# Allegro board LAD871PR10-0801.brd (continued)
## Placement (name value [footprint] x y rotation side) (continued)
EC9717  1000P_0402_50V7K  [C_0402]  123.63 147.27 270 top
EC9719  1U_0402_10V6K  [C_0402]  95.1 114.3 0 bottom
EC9720  1U_0402_10V6K  [C_0402]  95.1 119.25 0 bottom
EC9732  1U_0402_10V6K  [C_0402]  55.04 26.61 0 bottom
EC9733  1U_0402_10V6K  [C_0402]  158.18 52.01 180 top
EC9735  1U_0402_10V6K  [C_0402]  83.95 152.53 180 bottom
EC9736  1U_0402_10V6K  [C_0402]  83.95 149.73 180 bottom
EC9755  0.1U_0402_25V6  [C_0402]  167.88 120.47 315 bottom
EC9756  0.1U_0402_25V6  [C_0402]  168.9 121.35 315 bottom
EC9758  10P_0402_50V8J  [C_0402]  30.17 18.48 180 top
EC9759  0.1U_0402_25V6  [C_0402]  71.15 158.41 180 top
EC9760  0.1U_0402_25V6  [C_0402]  50.54 63.26 180 bottom
ED6101  -  [AZ5725-01F_DFN2]  192 175.07 180 top
EU3101  -  [TVWDF1004AD0_DFN9]  36.92 173.15 90 bottom
EU3102  -  [TVWDF1004AD0_DFN9]  37.28 173.15 90 top
EU3403  -  [AZC199-02SPR7G_SOT23-3]  22.07 38.07 90 top
EU5602  -  [L05ESDL5V0NA-4_SLP2510P8-10-9]  185.7 32.62 270 bottom
F5201  SMD1812P150TF/24 1.5A UL/CSA/TUV  [F_SMD1812P110TF-24]  73.07 162.18 0 bottom
F5203  1.1A_24V_SMD1812P110TF-24  [F_SMD1812P110TF-24]  92.25 153.35 0 bottom
F5501  1.1A_6V_SPR-P110  [F_SPR-P110]  19.02 70.23 0 top
F6201  0.5A_13.2V_NANOSMDC050F-13.2-2  [F_NANOSMDC050F-13P2-2]  183.8 119.89 180 bottom
FAN1  E-T_3703K-Q03N-11L  [E-T_3703K-Q03N-11L_3P]  92.47 136.72 24.9 bottom
FAN261  -  [APL5606AKI-TRG_SO8]  97.95 143.73 90 bottom
FD1  FIDUCAL  [FIDUCIAL_C40M80]  30.46 5.36 180 bottom
FD2  FIDUCIAL  [FIDUCIAL_C40M80]  38.79 10.62 0 top
FD3  FIDUCAL  [FIDUCIAL_C40M80]  201.54 177.23 180 bottom
FD4  FIDUCIAL  [FIDUCIAL_C40M80]  201.54 177.23 0 top
FD5  FIDUCAL  [FIDUCIAL_C40M80]  66.33 170 0 top
FD6  FIDUCIAL  [FIDUCIAL_C40M80]  200.34 3.17 180 bottom
G6101  GAP-OPEN  [SHORTPADS]  193.6 173.35 180 top
G6102  GAP-OPEN  [SHORTPADS]  191.4 176.05 270 bottom
H1  H_3P2  [H_3P2-G]  142.05 165.77 0 top
H2  H_3P0  [H_3P0-G]  169.65 12.77 0 top
H3  H_3P0  [H_3P0-G]  20.65 50.77 0 top
H4  H_3P0  [H_3P0-G]  96.65 128.47 0 top
H5  H_3P0  [H_3P0-G]  37.75 164.77 0 top
H6  H_3P2  [H_3P2-G]  199.85 56.27 0 top
H7  H_3P0  [H_3P0-G]  154.25 60.97 0 top
H8  -  [H_4P0N]  148.45 163.97 0 top
H9  -  [H_3P0X3P8N]  6.15 79.07 90 top
HCPU1  -  [H_3P7]  145.35 70.77 0 top
HCPU2  -  [H_3P7]  90.95 70.77 0 top
HCPU3  -  [H_3P4]  118.15 105.07 0 top
HDA27  ALC3246-CG_MQFN_48P  [ALC3234-CG_MQFN48_6X6-S]  180.52 14.09 90 bottom
HDD1  ACES_51625-01201-001  [ACES_51625-01201-001_12P]  191.37 33.63 270 bottom
HGPU1  -  [H_3P3]  143.25 148.69 0 top
HGPU2  -  [H_3P3]  201.25 114.27 0 bottom
HGPU3  -  [H_3P3]  200.85 158.69 180 bottom
J10  PAD-OPEN1X2M  [JUMP_43X39]  139.38 153.24 270 top
J11  -  [JUMP_43X118]  147.72 154.37 0 top
J12  -  [JUMP_43X118]  187.8 120.27 180 bottom
JCRT  C-K_80461-5K1-152  [C-K_80461-5K1-152_15P-T]  13.8 60.89 90 bottom
JDEG1  ACES_51522-01001-001  [ACES_51522-01001-001_10P]  191.95 90.11 270 bottom
JDIMM1  DEREN_40-42271-26001RHF  [DEREN_40-42271-26001RHF_260P-T]  78.12 38.99 0 bottom
JDIMM2  DEREN_40-42261-26001RHF  [DEREN_40-42261-26001RHF_260P-T]  86.72 24.66 180 bottom
JHDMI  ACON_HMRBK-AK120C~D  [C-K_96067-3K28-192-124_19P]  9.9 60.72 90 bottom
JWDB1  CVILU_CI1804M1VRA-NH  [CVILU_CI1804M1VRA-NH_4P]  155.85 51.8 180 bottom
KB1  CVILU_CF32301D0R0-NH  [CVILU_CF32301D0R0-NH_30P-T]  192.05 116.15 270 top
KB_BL1  E-T_6913K-Y04N-00L  [E-T_6913K-Y04N-00L_4P]  192.05 121.57 90 top
L3001  4.7UH_ZADH-252012MES-4R7M  [ZEN_ZADH-252012MES-4R7M_2P]  52.7 174.12 90 top
L5501  CHILISIN NBQ160808T-800Y-N 0603  [MURAT_BLM18BB221SN1D_2P]  22.14 61.88 180 top
L5502  CHILISIN NBQ160808T-800Y-N 0603  [MURAT_BLM18BB221SN1D_2P]  22.14 64.04 180 top
L5503  CHILISIN NBQ160808T-800Y-N 0603  [MURAT_BLM18BB221SN1D_2P]  22.14 59.15 180 top
LCD1  ACES_51540-04001-P01  [ACES_51540-04001-P01_40P]  80.8 165.93 0 bottom
LED1  12-22A/Y2T7D-C30/2C YELLOW/WHITE  [LED_12-22A-S2ST3D-C30-2C_3P]  16.54 1.78 180 top
LOM30  RTL8106E-CG_QFN32_4X4  [RTL8106E-CG_QFN32_4X4-S]  47.23 170.4 270 top
LV2  BLM15BD121SN1D_0402  [R_0402]  151.82 125.6 315 top
LV3  BLM15BD121SN1D_0402  [R_0402]  149.41 128.27 315 top
LV4  BLM15BD121SN1D_0402  [R_0402]  151.06 124.46 135 bottom
LV6  BLM15BD221SN1D_2P  [MURAT_BLM15BB221SN1D_2P]  171 129.54 135 top
LV7  BLM15BD121SN1D_0402  [R_0402]  178.11 128.91 45 top
LV8  BLM15BD121SN1D_0402  [R_0402]  178.86 128.13 45 top
NOREF  -  []  93.9 -40.25 0 top
NOREF#2  -  []  84.55 55.6 0 top
NOREF#3  -  []  200.85 158.69 0 top
NOREF#4  -  []  201.25 114.27 270 top
NOREF#5  -  []  54.41 5.27 0 top
NOREF#6  -  []  96.65 128.47 90 top
NOREF#7  -  []  143.25 148.69 0 top
NOREF#8  -  []  90.95 70.77 270 top
NOREF#9  -  []  107.75 60.79 0 top
NOREF#10  -  []  142.05 165.77 0 top
NOREF#11  -  []  8.96 446.38 0 top
NOREF#12  -  []  20.65 50.77 90 top
NOREF#13  -  []  146.42 8.76 0 top
NOREF#14  -  []  196.65 5.01 0 top
NOREF#15  -  []  169.65 12.77 270 top
NOREF#16  -  []  145.35 70.77 90 top
NOREF#17  -  []  118.15 105.07 270 top
NOREF#18  -  []  169.65 12.77 0 top
NOREF#19  -  []  154.25 60.97 0 top
NOREF#20  -  []  37.75 164.77 180 top
NOREF#21  -  []  4.72 257.97 0 top
NOREF#22  -  []  99.31 13.27 0 top
NOREF#23  -  []  201.25 114.27 0 top
NOREF#24  -  []  200.85 158.67 270 top
NOREF#25  -  []  96.65 128.47 90 top
NOREF#26  -  []  199.85 56.27 0 top
NOREF#27  -  []  90.35 76.83 180 bottom
NOREF#28  -  []  197.07 177.44 180 bottom
NOREF#29  -  []  143.25 148.67 90 bottom
NOREF#30  -  []  82.83 48.61 180 bottom
NOREF#31  -  []  213.55 158.67 90 bottom
NOREF#32  -  []  131.95 53.86 180 bottom
ODD1  ACES_51519-02001-P01  [ACES_51519-02001-P01_20P]  155.4 76.58 90 top
PBATT1  SUYIN_200277GR008M270ZR  [SUYIN_200277GR008M270ZR_8P-T]  152.4 179.77 0 bottom
PC1  1000P_0402_50V7K  [C_0402]  83.33 158.08 270 top
PC2  2200P_0402_25V7K  [C_0402]  82.44 158.08 270 top
PC3  1000P_0402_50V7K  [C_0402]  76.63 158.94 270 top
PC4  2200P_0402_25V7K  [C_0402]  77.51 158.94 270 top
PC7  0.01U_0402_25V7K  [C_0402]  150.48 172.59 0 top
PC8  1000P_0402_50V7K  [C_0402]  153.17 172.59 180 top
PC14  .1U_0402_16V7K  [C_0402]  146.49 171.15 270 top
PC16  .1U_0402_16V7K  [C_0402]  118.29 168.83 90 top
PC100  0.1U_0402_25V6  [C_0402]  31.92 43.24 0 bottom
PC102  0.1U_0402_10V7K  [C_0402]  28.79 36.46 0 bottom
PC103  2200P_0402_50V7K  [C_0402]  31.92 44.2 0 bottom
PC104  10U_0805_25V6K~D  [C_0805]  31.11 41.87 0 bottom
PC105  10U_0805_25V6K~D  [C_0805]  31.11 41.87 0 top
PC106  22U_0805_6.3V6M  [C_0805]  36.61 26.77 0 bottom
PC107  22U_0805_6.3V6M  [C_0805]  36.33 30 90 bottom
PC108  22U_0805_6.3V6M  [C_0805]  36.63 28.47 0 bottom
PC109  22U_0805_6.3V6M  [C_0805]  34.54 26.52 0 top
PC110  22U_0805_6.3V6M  [C_0805]  34.61 29.98 90 bottom
PC111  4.7U_0603_6.3V6M  [C_0603]  37.88 36.68 270 bottom
PC112  680P_0603_50V7K  [C_0603]  36.71 35.13 180 bottom
PC113  1000P_0402_25V8J  [C_0402]  37.05 40.68 0 bottom
PC114  0.1U_0402_10V7K  [C_0402]  40.39 36.45 0 bottom
PC115  0.1U_0402_25V6  [C_0402]  43.47 43.08 0 bottom
PC116  2200P_0402_50V7K  [C_0402]  43.47 43.97 0 bottom
PC117  10U_0805_25V6K~D  [C_0805]  42.58 41.76 0 bottom
PC118  10U_0805_25V6K~D  [C_0805]  42.59 41.75 0 top
PC119  4.7U_0603_6.3V6M  [C_0603]  48.65 35.86 0 bottom
PC120  22U_0805_6.3V6M  [C_0805]  47.86 27.81 270 bottom
PC121  22U_0805_6.3V6M  [C_0805]  49.59 27.81 270 bottom
PC122  22U_0805_6.3V6M  [C_0805]  51.72 31.95 0 bottom
PC123  22U_0805_6.3V6M  [C_0805]  47.78 29.24 90 bottom
PC124  22U_0805_6.3V6M  [C_0805]  49.64 29.24 90 bottom
PC125  680P_0603_50V7K  [C_0603]  48.57 34.67 180 bottom
PC126  4.7U_0603_6.3V6M  [C_0603]  48.65 37.08 0 bottom
PC127  1000P_0402_25V8J  [C_0402]  48.77 40.72 0 bottom
PC128  4.7U_0402_6.3V6M  [C_0402]  48.7 41.02 0 top
PC130  0.1U_0402_25V6  [C_0402]  31.87 44.14 0 top
PC131  2200P_0402_50V7K  [C_0402]  31.86 43.18 0 top
PC132  0.1U_0402_25V6  [C_0402]  43.43 43.95 0 top
PC133  2200P_0402_50V7K  [C_0402]  43.41 43.05 0 top
PC200  0.1U_0402_10V7K  [C_0402]  63.05 17.84 180 top
PC201  2200P_0402_50V7K  [C_0402]  69.64 19.43 0 bottom
PC202  0.1U_0402_10V7K  [C_0402]  55.31 22.19 180 top
PC203  0.1U_0402_10V7K  [C_0402]  55.31 23.08 180 top
PC204  1U_0603_10V6K  [C_0603]  57.78 15.88 90 top
PC205  10U_0805_6.3V6K  [C_0805]  62.48 21.65 0 top
PC206  10U_0805_25V6K~D  [C_0805]  69.44 16.19 0 top
PC207  680P_0402_50V7K  [C_0402]  71.68 21.97 270 bottom
PC208  0.1U_0402_25V6  [C_0402]  69.64 20.32 0 bottom
PC209  1U_0603_10V6K  [C_0603]  55.3 18.48 180 top
PC210  0.033U_0402_16V7K  [C_0402]  58.1 24.19 90 top
PC211  10U_0805_6.3V6K  [C_0805]  62.48 23.43 0 top
PC212  10U_0805_25V6K~D  [C_0805]  69.44 17.97 0 top
PC213  .1U_0402_16V7K  [C_0402]  57.22 25.97 180 top
PC214  220P_0402_25V8J  [C_0402]  56.31 24.19 0 top
PC215  22U_0603_6.3V6M  [C_0603]  77.21 22.99 180 top
PC216  22U_0603_6.3V6M  [C_0603]  80.19 22.99 0 top
PC217  22U_0603_6.3V6M  [C_0603]  80.19 21.72 0 top
PC218  22U_0603_6.3V6M  [C_0603]  80.19 20.45 0 top
PC219  22U_0603_6.3V6M  [C_0603]  77.21 20.32 180 top
PC220  22U_0603_6.3V6M  [C_0603]  77.21 21.65 180 top
PC230  0.1U_0402_25V6  [C_0402]  69.65 20.33 0 top
PC231  2200P_0402_50V7K  [C_0402]  69.65 19.4 0 top
PC301  2200P_0402_50V7K  [C_0402]  129.27 130.49 0 top
PC302  0.1U_0402_25V6  [C_0402]  129.28 129.55 0 top
PC303  10U_0805_25V6K~D  [C_0805]  129.15 128.04 0 bottom
PC304  0.1U_0402_25V6  [C_0402]  131.95 127.51 90 top
PC305  1U_0402_6.3V6K  [C_0402]  134.3 123.44 0 bottom
PC306  2.2U_0402_6.3V6M  [C_0402]  134.3 122.49 0 bottom
PC307  0.1U_0402_10V7K  [C_0402]  126.65 122.83 0 bottom
PC308  680P_0603_50V7K  [C_0603]  126.88 117.64 270 bottom
PC309  330P_0402_50V7K  [C_0402]  134.35 125.31 90 bottom
PC310  22U_0603_6.3V6M  [C_0603]  134.47 114.16 180 bottom
PC311  22U_0603_6.3V6M  [C_0603]  134.47 115.37 180 bottom
PC312  22U_0603_6.3V6M  [C_0603]  136.49 118.64 90 top
PC313  22U_0603_6.3V6M  [C_0603]  136.51 118.66 90 bottom
PC320  2200P_0402_50V7K  [C_0402]  129.28 130.49 0 bottom
PC321  0.1U_0402_25V6  [C_0402]  129.28 129.54 0 bottom
PC501  22U_0603_6.3V6M  [C_0603]  169.73 23.62 90 bottom
PC502  0.1U_0402_10V7K  [C_0402]  175.44 25.67 270 bottom
PC503  22P_0402_50V8J  [C_0402]  174.53 23.7 270 bottom
PC504  680P_0402_50V7K  [C_0402]  168.85 31.69 180 bottom
PC505  22U_0603_6.3V6M  [C_0603]  175.76 33.85 0 bottom
PC506  22U_0603_6.3V6M  [C_0603]  175.75 32.58 0 bottom
PC507  22U_0603_6.3V6M  [C_0603]  175.76 31.3 0 bottom
PC601  680P_0402_50V7K  [C_0402]  122.99 137.55 90 top
PC602  0.1U_0402_25V6  [C_0402]  114.75 144.48 180 bottom
PC603  1U_0603_10V6K  [C_0603]  115.97 143.7 270 bottom
PC604  0.22U_0603_25V7K  [C_0603]  123.63 145.67 270 bottom
PC605  47P_0402_50V8J~D  [C_0402]  110.41 145.8 0 bottom
PC606  33U_25V_M  [C_25CL33LD]  106.48 127.8 270 bottom
PC608  10U_0805_25V6K~D  [C_0805]  120.07 127.89 0 top
PC611  0.22U_0402_16V7K  [C_0402]  120.01 131.76 90 bottom
PC612  10U_0805_25V6K~D  [C_0805]  119.98 127.89 0 bottom
PC613  330P_0402_50V8J  [C_0402]  114.3 141.83 180 bottom
PC614  2200P_0402_50V7K  [C_0402]  114.28 140.08 270 bottom
PC616  33P_0402_50V8J  [C_0402]  114.31 140.93 180 bottom
PC617  220P_0402_50V7K  [C_0402]  110.04 139.7 180 top
PC618  330P_0402_50V7K  [C_0402]  110.93 144.37 270 bottom
PC619  0.01U_0402_50V7K  [C_0402]  111.82 144.37 270 bottom
PC620  0.082U_0402_16V7K  [C_0402]  110.92 142.58 0 bottom
PC621  1000P_0402_50V7K  [C_0402]  111.01 142.52 180 top
PC622  680P_0603_50V7K  [C_0603]  124.33 122.3 90 bottom
PC624  0.01U_0402_16V7K  [C_0402]  111.94 139.2 270 bottom
PC625  330P_0402_50V7K  [C_0402]  115.69 138.02 270 bottom
PC626  0.1U_0402_25V7K  [C_0402]  111.05 139.2 270 bottom
PC627  2200P_0402_50V7K  [C_0402]  110.98 138.71 0 top
PC628  10P_0402_50V8J  [C_0402]  119.5 140.2 180 bottom
PC629  2200P_0402_50V7K  [C_0402]  119.26 137.35 180 bottom
PC630  2200P_0402_50V7K  [C_0402]  119.87 135.47 0 top
PC631  1200P_0402_50V7K  [C_0402]  118.56 142.08 270 bottom
PC632  2200P_0402_25V7K  [C_0402]  121.14 141.44 0 top
PC633  6800P_0402_25V7K  [C_0402]  121.2 141.5 0 bottom
PC635  0.022U_0402_16V7K  [C_0402]  110.99 136.93 0 top
PC636  33P_0402_50V8J  [C_0402]  116.58 137.92 270 bottom
PC637  0.033U_0402_16V7K  [C_0402]  121.2 143.28 0 bottom
PC638  0.022U_0402_16V7K  [C_0402]  110.99 135.79 0 top
PC639  2200P_0402_25V7K  [C_0402]  116.82 134.57 270 top
PC640  2200P_0402_25V7K  [C_0402]  122.11 139.39 90 top
PC641  .1U_0402_16V7K  [C_0402]  109.28 138.29 90 bottom
PC642  0.068U_0402_16V7K  [C_0402]  119.97 135.46 270 bottom
PC643  330P_0402_50V7K  [C_0402]  119.5 139.31 180 bottom
PC644  .1U_0402_16V7K  [C_0402]  122.1 144.2 90 bottom
PC645  .1U_0402_16V7K  [C_0402]  120.85 134.72 0 bottom
PC646  0.033U_0402_16V7K  [C_0402]  119.08 135.46 270 bottom
PC647  680P_0402_50V7K  [C_0402]  118.12 132.77 180 top
PC649  0.01U_0402_50V7K  [C_0402]  122.05 137.54 180 bottom
PC650  0.082U_0402_16V7K  [C_0402]  121.22 139.42 270 bottom
PC651  330P_0402_50V7K  [C_0402]  118.1 133.68 90 top
PC652  330P_0402_50V7K  [C_0402]  122.11 139.42 270 bottom
PC653  0.082U_0402_16V7K  [C_0402]  118.09 135.47 0 top
PC654  0.01U_0402_50V7K  [C_0402]  118.99 133.68 90 top
PC655  0.22U_0402_16V7K  [C_0402]  115.5 130.75 270 bottom
PC656  10U_0805_25V6K~D  [C_0805]  115.88 127.2 270 bottom
PC657  10U_0805_25V6K~D  [C_0805]  117.63 127.2 270 bottom
PC658  10U_0805_25V6K~D  [C_0805]  115.82 127.22 270 top
PC659  0.1U_0402_25V6K~D  [C_0402]  119.06 126.62 270 top
PC660  2200P_0402_50V7K  [C_0402]  117.21 126.63 270 top
PC661  1U_0402_10V6K  [C_0402]  113.09 129.54 90 bottom
PC662  680P_0603_50V7K  [C_0603]  110.99 122.68 90 top
PC663  0.22U_0402_16V7K  [C_0402]  58.32 43.89 90 bottom
PC664  10U_0805_25V6K~D  [C_0805]  58.1 46.86 90 top
PC665  10U_0805_25V6K~D  [C_0805]  57.92 46.86 90 bottom
PC666  0.1U_0402_25V6K~D  [C_0402]  63.23 40.88 90 bottom
PC667  2200P_0402_50V7K  [C_0402]  64.12 40.88 90 bottom
PC668  0.1U_0402_25V6K~D  [C_0402]  56.6 46.99 90 bottom
PC669  1U_0402_10V6K  [C_0402]  62.03 44.15 0 bottom
PC670  680P_0603_50V7K  [C_0603]  59.04 51.46 270 top
PC671  0.22U_0402_16V7K  [C_0402]  67.11 36.45 90 bottom
PC672  10U_0805_25V6K~D  [C_0805]  65.59 39.98 90 top
PC673  10U_0805_25V6K~D  [C_0805]  65.46 39.98 90 bottom
PC674  2200P_0402_50V7K  [C_0402]  55.71 46.99 90 bottom
PC677  1U_0402_10V6K  [C_0402]  69.78 37.35 270 bottom
PC678  680P_0603_50V7K  [C_0603]  70.8 45.34 270 top
PC679  1000P_0402_50V7K  [C_0402]  63.24 40.88 90 top
PC680  1000P_0402_50V7K  [C_0402]  118.1 126.63 270 top
PC681  1000P_0402_50V7K  [C_0402]  54.82 46.99 90 bottom
PC682  2200P_0402_50V7K  [C_0402]  55.89 46.99 90 top
PC683  0.1U_0402_25V6K~D  [C_0402]  56.78 46.99 90 top
PC684  0.1U_0402_25V6  [C_0402]  71.82 39.71 270 bottom
PC685  1U_0402_10V6K  [C_0402]  124.2 129.34 90 bottom
PC686  10P_0402_25V8J  [C_0402]  108.39 126.24 270 top
PC687  10P_0402_25V8J  [C_0402]  55 46.99 90 top
PC688  10P_0402_25V8J  [C_0402]  64.19 40.88 90 top
PC690  33U_25V_M  [C_25CL33LD]  61.96 38.02 180 bottom
PC691  2200P_0402_50V7K  [C_0402]  109.28 126.24 270 top
PC692  0.1U_0402_25V6K~D  [C_0402]  59.58 41.96 0 bottom
PC693  2200P_0402_50V7K  [C_0402]  59.58 42.84 0 bottom
PC694  0.1U_0402_25V6K~D  [C_0402]  118.93 126.62 270 bottom
PC695  10P_0402_25V8J  [C_0402]  114.85 146.49 0 top
PC705  2200P_0402_25V7K  [C_0402]  120.97 152.84 180 top
PC708  0.1U_0402_25V6  [C_0402]  109.82 162.77 0 bottom
PC711  0.01UF_0402_25V7K  [C_0402]  80.07 169.21 90 top
PC721  0.22U_0402_16V7K  [C_0402]  116.02 157.35 180 bottom
PC742  5600P_0402_25V7K  [C_0402]  78.52 164.47 180 top
PC744  0.1U_0402_25V6  [C_0402]  78.52 166.5 180 top
PC747  0.1U_0402_25V6  [C_0402]  108.46 154.81 180 bottom
PC748  0.1U_0402_25V7K  [C_0402]  104.07 158.83 270 bottom
PC749  0.1U_0402_25V7K  [C_0402]  104.07 160.6 270 bottom
PC750  0.22U_0603_25V7K  [C_0603]  110.74 154.69 180 bottom
PC751  560P_0402_50V7K  [C_0402]  103.68 162.75 0 bottom
PC752  0.015U_0402_25V7K  [C_0402]  103.68 163.64 0 bottom
PC753  10P_0402_50V8J  [C_0402]  109.91 160.32 90 top
PC757  1U_0603_25V6  [C_0603]  114.36 159.32 90 bottom
PC760  10U_0805_25V6K~D  [C_0805]  124.63 157.4 0 top
PC761  10U_0805_25V6K~D  [C_0805]  135.67 162.28 90 bottom
PC762  10U_0805_25V6K~D  [C_0805]  124.55 153.87 0 top
PC763  10U_0805_25V6K~D  [C_0805]  124.63 155.63 0 top
PC764  10U_0805_25V6K~D  [C_0805]  124.55 152.15 0 top
PC765  0.1U_0402_25V7K  [C_0402]  120.97 153.73 180 top
PC766  10U_0805_25V6K~D  [C_0805]  132.11 162.28 90 bottom
PC767  680P_0603_50V7K  [C_0603]  126.23 162.75 270 top
PC768  1U_0402_16V6K  [C_0402]  111.82 159.44 90 top
PC769  1U_0402_16V6K  [C_0402]  111.68 158.56 0 top
PC775  10U_0805_25V6K~D  [C_0805]  133.91 162.28 90 bottom
PC776  10U_0805_25V6K~D  [C_0805]  135.79 160.78 0 bottom
PC777  0.1U_0402_25V7K  [C_0402]  134.75 158.83 270 bottom
PC778  10U_0805_25V6K~D  [C_0805]  135.82 159.03 0 bottom
PC779  0.1U_0402_25V7K  [C_0402]  130.97 155.87 270 top
PC780  0.1U_0402_25V7K  [C_0402]  121.03 150.93 180 top
PC781  2200P_0402_25V7K  [C_0402]  121.03 151.89 180 top
PC790  0.047U_0402_16V7K  [C_0402]  68.13 160.91 270 top
PC801  1U_0402_6.3V6K  [C_0402]  59.23 33.05 0 bottom
PC802  10U_0805_10V6K  [C_0805]  57.7 30.5 90 bottom
PC803  0.01U_0402_25V7K  [C_0402]  66.51 30.49 270 bottom
PC804  10U_0805_10V6K  [C_0805]  67.03 31.71 90 bottom
PC805  0.1U_0402_10V6K  [C_0402]  57.21 29.22 270 bottom
PC836  330U_2V_M  [C_5X4P5]  188.74 95.97 90 bottom
PC837  330U_2V_M  [C_5X4P5]  188.06 100.96 180 bottom
PC838  330U_2V_M  [C_5X4P5]  188.06 107.06 180 bottom
PC839  330U_2V_M  [C_5X4P5]  186.28 113.16 180 bottom
PC1001  22U_0603_6.3V6M  [C_0603]  115.99 88.71 0 top
PC1002  22U_0603_6.3V6M  [C_0603]  115.99 89.92 0 top
PC1003  22U_0603_6.3V6M  [C_0603]  106.94 112.26 0 top
PC1004  22U_0603_6.3V6M  [C_0603]  118.4 86.3 0 top
PC1005  22U_0603_6.3V6M  [C_0603]  101.13 111.38 0 top
PC1006  22U_0603_6.3V6M  [C_0603]  110.18 112.33 0 top
PC1007  22U_0603_6.3V6M  [C_0603]  101.15 110.05 0 top
PC1008  22U_0603_6.3V6M  [C_0603]  113.23 112.07 0 top
PC1009  22U_0603_6.3V6M  [C_0603]  105.04 109.66 180 top
PC1010  22U_0603_6.3V6M  [C_0603]  115.99 85.03 0 top
PC1011  22U_0603_6.3V6M  [C_0603]  114.85 87.5 180 top
PC1012  22U_0603_6.3V6M  [C_0603]  118.4 85.03 0 top
PC1013  22U_0603_6.3V6M  [C_0603]  110.18 107.25 0 top
PC1014  22U_0603_6.3V6M  [C_0603]  95.26 86.32 90 top
PC1015  22U_0603_6.3V6M  [C_0603]  61.72 68.64 180 top
PC1016  22U_0603_6.3V6M  [C_0603]  83.36 83.22 135 bottom
PC1017  22U_0603_6.3V6M  [C_0603]  61.68 69.89 180 bottom
PC1018  22U_0603_6.3V6M  [C_0603]  80.38 78.61 315 bottom
PC1019  22U_0603_6.3V6M  [C_0603]  61.69 68.64 180 bottom
PC1020  22U_0603_6.3V6M  [C_0603]  87.78 86.3 90 top
PC1021  22U_0603_6.3V6M  [C_0603]  90.25 86.3 90 top
PC1022  22U_0603_6.3V6M  [C_0603]  110.97 90.58 270 top
PC1023  22U_0603_6.3V6M  [C_0603]  81.27 79.44 315 top
PC1024  22U_0603_6.3V6M  [C_0603]  92.72 86.32 90 top
PC1025  22U_0603_6.3V6M  [C_0603]  91.56 89.38 90 top
PC1026  22U_0603_6.3V6M  [C_0603]  108.19 82.47 90 top
PC1027  22U_0603_6.3V6M  [C_0603]  108.56 80.8 0 top
PC1028  22U_0603_6.3V6M  [C_0603]  96.41 89.37 90 top
PC1029  22U_0603_6.3V6M  [C_0603]  93.99 89.37 90 top
PC1030  1U_0201_6.3V6M  [C_0201]  115.89 82.75 180 top
PC1031  1U_0201_6.3V6M  [C_0201]  120.86 87.59 0 top
PC1032  1U_0201_6.3V6M  [C_0201]  114.64 82.78 180 top
PC1033  1U_0201_6.3V6M  [C_0201]  117.58 82.8 0 top
PC1034  1U_0201_6.3V6M  [C_0201]  101.11 107.38 0 top
PC1035  1U_0201_6.3V6M  [C_0201]  120.21 93.52 180 top
PC1036  1U_0201_6.3V6M  [C_0201]  101.11 105.47 0 top
PC1037  1U_0201_6.3V6M  [C_0201]  120.86 88.23 0 top
PC1038  1U_0201_6.3V6M  [C_0201]  119.14 81.1 180 top
PC1039  1U_0201_6.3V6M  [C_0201]  101.11 106.74 0 top
PC1040  1U_0201_6.3V6M  [C_0201]  105.24 76.83 0 top
PC1041  1U_0201_6.3V6M  [C_0201]  107.29 81.15 270 top
PC1042  1U_0201_6.3V6M  [C_0201]  105.94 73.34 0 top
PC1043  1U_0201_6.3V6M  [C_0201]  102.08 95.19 180 top
PC1044  1U_0201_6.3V6M  [C_0201]  101.82 76.33 180 top
PC1045  1U_0201_6.3V6M  [C_0201]  111.61 81.17 270 top
PC1046  1U_0201_6.3V6M  [C_0201]  98.82 91 0 top
PC1047  1U_0201_6.3V6M  [C_0201]  112.79 82.33 0 top
PC1048  1U_0201_6.3V6M  [C_0201]  112.79 82.91 0 top
PC1049  1U_0201_6.3V6M  [C_0201]  100.3 97.98 180 top
PC1050  1U_0201_6.3V6M  [C_0201]  120.26 92.46 180 top
PC1051  1U_0201_6.3V6M  [C_0201]  117.72 81.1 180 top
PC1052  1U_0201_6.3V6M  [C_0201]  120.44 81 0 top
PC1053  1U_0201_6.3V6M  [C_0201]  119.14 80.54 180 top
PC1054  1U_0201_6.3V6M  [C_0201]  117.72 80.54 180 top
PC1055  1U_0201_6.3V6M  [C_0201]  112.47 81.17 270 top
PC1056  1U_0201_6.3V6M  [C_0201]  105.94 75.18 0 top
PC1057  22U_0603_6.3V6M  [C_0603]  123.61 89.81 180 top
PC1058  22U_0603_6.3V6M  [C_0603]  124.56 87.97 0 top
PC1059  22U_0603_6.3V6M  [C_0603]  119.29 111.51 180 top
PC1060  22U_0603_6.3V6M  [C_0603]  123.63 111.4 180 top
PC1061  22U_0603_6.3V6M  [C_0603]  105.04 110.93 180 top
PC1062  330U_2V_M  [C_5X4P5]  108.04 106.41 0 bottom
PC1063  330U_2V_M  [C_5X4P5]  66.05 57.26 180 bottom
PC1064  22U_0603_6.3V6M  [C_0603]  101.15 108.71 0 top
PC1065  22U_0603_6.3V6M  [C_0603]  105.04 112.2 180 top
PC1066  22U_0603_6.3V6M  [C_0603]  114.85 83.82 180 top
PC1067  22U_0603_6.3V6M  [C_0603]  118.4 83.82 0 top
PC1068  22U_0603_6.3V6M  [C_0603]  106.94 110.99 0 top
PC1069  22U_0603_6.3V6M  [C_0603]  114.85 86.3 180 top
PC1070  22U_0603_6.3V6M  [C_0603]  106.94 107.18 0 top
PC1071  22U_0603_6.3V6M  [C_0603]  105.08 107.11 180 top
PC1072  22U_0603_6.3V6M  [C_0603]  106.94 108.45 0 top
PC1073  22U_0603_6.3V6M  [C_0603]  113.23 110.8 0 top
PC1074  22U_0603_6.3V6M  [C_0603]  118.4 89.92 0 top
PC1075  22U_0603_6.3V6M  [C_0603]  110.18 111.06 0 top
PC1076  22U_0603_6.3V6M  [C_0603]  110.18 109.79 0 top
PC1077  22U_0603_6.3V6M  [C_0603]  105.04 108.39 180 top
PC1078  22U_0603_6.3V6M  [C_0603]  118.4 88.71 0 top
PC1079  22U_0603_6.3V6M  [C_0603]  114.85 88.71 180 top
PC1080  22U_0603_6.3V6M  [C_0603]  106.94 109.72 0 top
PC1081  22U_0603_6.3V6M  [C_0603]  114.85 85.03 180 top
PC1082  22U_0603_6.3V6M  [C_0603]  115.99 86.3 0 top
PC1083  1U_0201_6.3V6M  [C_0201]  106.17 104.53 0 top
PC1084  1U_0201_6.3V6M  [C_0201]  118.99 93.62 180 top
PC1085  1U_0201_6.3V6M  [C_0201]  101.11 106.11 0 top
PC1086  1U_0201_6.3V6M  [C_0201]  114.95 92.43 180 top
PC1087  1U_0201_6.3V6M  [C_0201]  115.79 93.52 0 top
PC1088  1U_0201_6.3V6M  [C_0201]  120.86 88.86 0 top
PC1089  1U_0201_6.3V6M  [C_0201]  106.14 105.79 0 top
PC1090  1U_0201_6.3V6M  [C_0201]  120.44 79.88 0 top
PC1091  1U_0201_6.3V6M  [C_0201]  120.21 94.11 180 top
PC1092  1U_0201_6.3V6M  [C_0201]  113.76 91.25 180 top
PC1093  1U_0201_6.3V6M  [C_0201]  120.44 80.44 0 top
PC1094  1U_0201_6.3V6M  [C_0201]  116.7 92.38 180 top
PC1095  1U_0201_6.3V6M  [C_0201]  120.86 86.96 0 top
PC1096  1U_0201_6.3V6M  [C_0201]  117.63 82.19 0 top
PC1097  1U_0201_6.3V6M  [C_0201]  118.53 92.25 180 top
PC1098  1U_0201_6.3V6M  [C_0201]  112.71 94.17 180 top
PC1099  1U_0201_6.3V6M  [C_0201]  106.11 105.1 0 top
PC1101  330U_2V_M  [C_5X4P5]  66.04 63.44 180 bottom
PC1103  10U_0805_25V6K~D  [C_0805]  166.68 111.72 270 top
PC1104  10U_0805_25V6K~D  [C_0805]  164.9 111.72 270 top
PC1105  10U_0805_25V6K~D  [C_0805]  167.57 112.17 270 bottom
PC1106  2200P_0402_50V7K  [C_0402]  166.11 97.59 90 bottom
PC1107  0.1U_0402_25V6K  [C_0402]  164.46 111.33 270 bottom
PC1108  0.22U_0402_16V7K  [C_0402]  165.73 105.03 180 bottom
PC1109  680P_0603_50V7K  [C_0603]  170.96 96.56 180 top
PC1110  1U_0603_10V6K  [C_0603]  161.58 108.53 180 top
PC1111  1U_0603_10V6K  [C_0603]  160.84 104.58 180 top
PC1112  10U_0805_25V6K~D  [C_0805]  166.55 97.07 90 top
PC1113  10U_0805_25V6K~D  [C_0805]  164.78 97.07 90 bottom
PC1114  10U_0805_25V6K~D  [C_0805]  164.78 97.07 90 top
PC1115  2200P_0402_50V7K  [C_0402]  166.24 111.33 270 bottom
PC1116  0.1U_0402_25V6  [C_0402]  167.89 97.59 90 bottom
PC1117  1000P_0402_50V7K  [C_0402]  153.95 110.31 0 bottom
PC1118  0.22U_0402_16V7K  [C_0402]  165.55 108.2 180 bottom
PC1119  0.22U_0402_10V6K  [C_0402]  155.81 112.98 270 bottom
PC1120  0.22U_0402_10V6K  [C_0402]  156.69 112.98 270 bottom
PC1121  680P_0603_50V7K  [C_0603]  170.96 111.79 180 top
PC1122  1000P_0402_50V7K  [C_0402]  159.89 111.24 90 bottom
PC1123  330P_0402_50V7K  [C_0402]  162.6 112.22 0 bottom
PC1124  330P_0402_50V7K  [C_0402]  158.85 110.76 270 top
PC1125  1U_0201_6.3V6M  [C_0201]  120.86 89.5 0 top
PC1126  1U_0201_6.3V6M  [C_0201]  113.59 91.86 90 top
PC1127  330U_2V_M  [C_5X4P5]  108.01 112.39 0 bottom
PC1128  330U_2V_M  [C_5X4P5]  61.14 63.8 0 bottom
PC1129  22U_0603_6.3V6M  [C_0603]  83 81.2 315 bottom
PC1130  22U_0603_6.3V6M  [C_0603]  110.64 82.47 90 top
PC1131  22U_0603_6.3V6M  [C_0603]  82.11 80.31 315 bottom
PC1132  22U_0603_6.3V6M  [C_0603]  81.25 79.44 315 bottom
PC1133  22U_0603_6.3V6M  [C_0603]  105.78 74.29 0 top
PC1134  22U_0603_6.3V6M  [C_0603]  95.2 89.37 90 top
PC1135  22U_0603_6.3V6M  [C_0603]  109.77 89.66 270 top
PC1136  22U_0603_6.3V6M  [C_0603]  79.5 77.72 315 bottom
PC1137  22U_0603_6.3V6M  [C_0603]  61.72 69.91 180 top
PC1138  22U_0603_6.3V6M  [C_0603]  82.49 82.38 135 top
PC1139  22U_0603_6.3V6M  [C_0603]  119.29 112.78 180 top
PC1140  22U_0603_6.3V6M  [C_0603]  123.61 112.72 180 top
PC1141  22U_0603_6.3V6M  [C_0603]  123.61 86.13 180 top
PC1142  22U_0603_6.3V6M  [C_0603]  124.71 111.44 90 top
PC1143  22U_0603_6.3V6M  [C_0603]  123.61 87.34 180 top
PC1144  22U_0603_6.3V6M  [C_0603]  123.61 88.61 180 top
PC1145  22U_0603_6.3V6M  [C_0603]  125.91 111.44 90 top
PC1146  22U_0603_6.3V6M  [C_0603]  123.61 84.86 180 top
PC1147  1U_0201_6.3V6M  [C_0201]  122.54 91.8 0 top
PC1148  1U_0201_6.3V6M  [C_0201]  124.37 86.13 0 top
PC1149  1U_0201_6.3V6M  [C_0201]  122.24 92.43 180 top
PC1150  1U_0201_6.3V6M  [C_0201]  123.76 90.73 180 top
PC1151  1U_0201_6.3V6M  [C_0201]  123.86 92.39 180 top
PC1152  1U_0201_6.3V6M  [C_0201]  122.47 90.73 180 top
PC1153  1U_0201_6.3V6M  [C_0201]  123.53 83.87 180 top
PC1154  22U_0603_6.3V6M  [C_0603]  93.99 86.32 90 top
PC1155  22U_0603_6.3V6M  [C_0603]  82.47 82.39 135 bottom
PC1156  22U_0603_6.3V6M  [C_0603]  61.69 67.37 180 bottom
PC1158  22U_0603_6.3V6M  [C_0603]  90.3 88.77 90 top
PC1159  22U_0603_6.3V6M  [C_0603]  92.76 89.38 90 top
PC1161  22U_0603_6.3V6M  [C_0603]  81.6 81.49 135 top
PC1162  22U_0603_6.3V6M  [C_0603]  89.1 88.77 90 top
PC1163  22U_0603_6.3V6M  [C_0603]  88.98 86.28 90 top
PC1164  1U_0201_6.3V6M  [C_0201]  120.86 90.13 0 top
PC1170  22U_0603_6.3V6M  [C_0603]  115.99 83.82 0 top
PC1171  22U_0603_6.3V6M  [C_0603]  110.18 108.52 0 top
PC1172  22U_0603_6.3V6M  [C_0603]  115.99 87.5 0 top
PC1173  22U_0603_6.3V6M  [C_0603]  118.4 87.5 0 top
PC1174  22U_0603_6.3V6M  [C_0603]  114.85 89.92 180 top
PC1175  22U_0603_6.3V6M  [C_0603]  91.47 86.32 90 top
PC1176  22U_0603_6.3V6M  [C_0603]  83.05 81.22 315 top
PC1177  22U_0603_6.3V6M  [C_0603]  112.24 90.58 270 top
PC1178  22U_0603_6.3V6M  [C_0603]  81.58 81.5 135 bottom
PC1179  22U_0603_6.3V6M  [C_0603]  97.61 89.37 90 top
PC1180  22U_0603_6.3V6M  [C_0603]  109.41 82.47 90 top
PC1181  22U_0603_6.3V6M  [C_0603]  86.57 86.3 90 top
PC1182  22U_0603_6.3V6M  [C_0603]  106.99 82.47 90 top
PC1183  22U_0603_6.3V6M  [C_0603]  79.5 77.72 315 top
PC1184  22U_0603_6.3V6M  [C_0603]  78.61 76.9 315 bottom
PC1190  2200P_0402_50V7K  [C_0402]  167 97.59 90 bottom
PC1191  0.1U_0402_25V6K  [C_0402]  163.57 111.58 270 top
PC1192  2200P_0402_50V7K  [C_0402]  165.35 111.33 270 bottom
PC1193  0.1U_0402_25V6  [C_0402]  163.44 97.27 90 top
PC1201  0.1U_0402_10V7K  [C_0402]  40.13 49.34 90 bottom
PC1202  0.1U_0402_25V6  [C_0402]  31.81 53.84 90 bottom
PC1203  10U_0603_25V6M  [C_0603]  33.84 53.72 90 bottom
PC1204  0.1U_0402_25V6  [C_0402]  36.7 56.82 90 bottom
PC1205  1U_0402_6.3V6K  [C_0402]  37.65 50.74 180 bottom
PC1206  22U_0603_6.3V6M  [C_0603]  49.71 57.47 180 bottom
PC1207  22U_0603_6.3V6M  [C_0603]  48.44 50.93 270 bottom
PC1208  22U_0603_6.3V6M  [C_0603]  49.65 50.93 270 bottom
PC1209  680P_0402_50V7K  [C_0402]  39.55 57.2 90 bottom
PC1210  2200P_0402_50V7K  [C_0402]  32.7 53.85 90 top
PC1211  0.1U_0402_25V6  [C_0402]  32.7 53.85 90 bottom
PC1212  2200P_0402_50V7K  [C_0402]  31.68 53.85 90 top
PC1221  22U_0603_6.3V6M  [C_0603]  80.38 78.61 315 top
PC1222  22U_0603_6.3V6M  [C_0603]  83.36 83.22 135 top
PC1223  22U_0603_6.3V6M  [C_0603]  61.72 67.37 180 top
PC1224  22U_0603_6.3V6M  [C_0603]  82.16 80.33 315 top
PC1226  0.1U_0402_25V6K  [C_0402]  154.8 106.75 180 bottom
PC1227  820P_0402_50V7K  [C_0402]  158.47 112.83 270 bottom
PC1228  390P_0402_50V7K  [C_0402]  163.51 114.01 270 bottom
PC1229  0.01U_0402_50V7K  [C_0402]  159.74 110.76 270 top
PC1230  0.15U_0603_16V7K  [C_0603]  155.23 114.05 0 bottom
PC1231  0.1U_0603_50V7K  [C_0603]  157.77 114.76 0 bottom
PC1232  0.033U_0402_16V7K  [C_0402]  156.82 115.18 90 bottom
PC1233  330P_0402_50V  [C_0402]  161.73 113.91 90 bottom
PC1401  2200P_0402_50V7K  [C_0402]  135.12 135.84 270 top
PC1402  0.1U_0402_25V6  [C_0402]  134.23 135.84 270 bottom
PC1403  10U_0805_25V6K~D  [C_0805]  132.85 136.37 270 bottom
PC1404  0.1U_0402_25V6  [C_0402]  127.37 135 270 bottom
PC1405  1U_0402_6.3V6K  [C_0402]  126.12 139.45 180 bottom
PC1406  2.2U_0402_6.3V6M  [C_0402]  128.57 140.72 0 top
PC1407  0.1U_0402_10V7K  [C_0402]  133.48 140.24 180 bottom
PC1408  680P_0603_50V7K  [C_0603]  131.5 143.19 270 top
PC1409  330P_0402_50V7K  [C_0402]  126.1 138.5 270 bottom
PC1411  22U_0603_6.3V6M  [C_0603]  136.07 148.21 270 bottom
PC1412  22U_0603_6.3V6M  [C_0603]  137.34 148.21 270 bottom
PC1413  22U_0603_6.3V6M  [C_0603]  134.8 148.21 270 bottom
PC1414  22U_0603_6.3V6M  [C_0603]  133.54 148.2 270 bottom
PC1420  2200P_0402_50V7K  [C_0402]  134.23 135.84 270 top
PC1421  0.1U_0402_25V6  [C_0402]  135.12 135.84 270 bottom
PC1422  0.1U_0402_25V6  [C_0402]  52.62 73.89 270 bottom
PC1423  0.1U_0402_25V6  [C_0402]  60.66 70.97 0 bottom
PC1424  0.1U_0402_25V6  [C_0402]  54.78 70.46 270 bottom
PD2  -  [TVNST52302AB0_SOT523-3]  157.73 174.12 90 top
PD3  -  [TVNST52302AB0_SOT523-3]  155.06 175.89 90 top
PD4  -  [TVNST52302AB0_SOT523-3]  93.66 156.65 180 top
PD5  -  [BAV99W_SC70-3]  94.16 149.13 0 top
PD6  -  [BAV99W_SC70-3]  89.56 151.13 90 top
PD102  -  [SDMK0340L-7-F_SOD323-2]  50.53 42.42 180 top
PD704  -  [LRB715FT1G_SOT323-3]  115.95 163.13 90 bottom
PH601  470K_0402_5%_ TSM0B474J4702RE  [R_0402]  71.76 43.75 90 bottom
PH602  10K_0402_5%_ERTJ0ER103J  [R_0402]  64.14 52.37 270 bottom
PH603  470K_0402_5%_ TSM0B474J4702RE  [R_0402]  115.83 123.29 270 bottom
PH604  10KB_0402_5%_ERTJ0ER103J  [R_0402]  124.49 116.46 270 bottom
PH605  10KB_0402_5%_ERTJ0ER103J  [R_0402]  117.13 115.34 270 bottom
PH1101  470K_0402_5%_TSM0B474J4702RE  [R_0402]  173.36 116.59 180 bottom
PH1102  10K_0402_5%_ERTJ0ER103J  [R_0402]  182.68 112.62 180 bottom
PJP1  JUMP_43X79  [JUMP_43X79-NPM]  81.08 160.46 0 top
PJP2  JUMP_43X79  [JUMP_43X79-NPM]  97.57 156.93 90 top
PJP3  JUMP_43X79  [JUMP_43X79-NPM]  152.37 175.01 180 top
PJP13  PAD-OPEN1X3M  [JUMP_43X118]  40.48 17.14 180 top
PJP15  -  [JUMP_43X79]  133.14 113.71 270 top
PJP21  PAD-OPEN1X3M  [JUMP_43X118]  50.79 15.52 90 top
PJP23  -  [JUMP_43X79]  151.57 87.54 270 top
PJP27  PAD-OPEN1X1M  [JUMP_43X39]  129.46 107.89 0 top
PJP32  PAD-OPEN1X3M  [JUMP_43X118]  127.9 113.54 0 top
PJP102  -  [JUMP_43X118]  29.62 24.65 270 bottom
PJP103  -  [JUMP_43X118]  52.18 28.42 0 bottom
PJP105  JUMP_43X79  [JUMP_43X79-NPM]  36.67 45.97 180 top
PJP106  JUMP_43X79  [JUMP_43X79-NPM]  41.83 47.02 270 top
PJP200  -  [JUMP_43X118]  78.38 24.91 90 top
PJP203  -  [JUMP_43X79]  59.64 25.46 0 top
PJP206  -  [JUMP_43X79]  69.97 24.53 90 top
PJP301  -  [JUMP_43X79]  126.42 130.79 270 top
PJP302  -  [JUMP_43X118]  137.6 114.52 270 bottom
PJP501  -  [JUMP_43X79]  171.89 20.79 90 bottom
PJP502  -  [JUMP_43X79]  172.33 36.34 90 bottom
PJP601  PAD-OPEN 4X4M  [JUMP_43X118-NPM]  109.85 131.53 90 bottom
PJP602  PAD-OPEN 4X4M  [JUMP_43X118-NPM]  59.11 37.72 270 top
PJP603  PAD-OPEN1X1M  [JUMP_43X39]  118.31 130.3 180 bottom
PJP701  JUMP_43X118  [JUMP_43X118-NPM]  120.72 154.1 0 bottom
PJP801  -  [JUMP_43X79]  53.52 35.31 270 bottom
PJP802  -  [JUMP_43X79]  69.2 31.57 0 bottom
PJP1101  JUMP_43X79  [JUMP_43X79-NPM]  150.93 118.79 270 top
PJP1201  JUMP_43X79  [JUMP_43X79-NPM]  32.95 49.72 90 top
PJP1202  -  [JUMP_43X79]  49.89 54.17 0 top
PJP1401  -  [JUMP_43X79]  136.21 138.56 180 top
PJP1402  -  [JUMP_43X118]  136.53 150.19 90 bottom
PJPDC1  ACES_50458-00601-001  [ACES_50458-00601-001_6P-T]  98.15 161.74 180 top
PL1  HCB3225KF-151T50_2P  [5A_Z150_1210_2P]  82.96 160.46 180 top
PL2  BLM15AG102SN1D_2P  [MURAT_BLM15AG102SN1D_2P]  93.27 159.83 0 top
PL3  HCB3225KF-151T50_2P  [5A_Z150_1210_2P]  150.47 174.98 0 top
PL4  HCB3225KF-151T50_2P  [5A_Z150_1210_2P]  97.52 158.83 270 top
PL100  1.5UH_9A_20%_7X7X3_M  [L_7X7X3_M_2P]  29.71 33.95 270 bottom
PL101  2.2UH_7.8A_20%_7X7X3_M  [L_7X7X3_M_2P]  42.78 33.76 270 bottom
PL102  HCB3225KF-151T50_2P  [5A_Z150_1210_2P]  37.47 45.97 180 top
PL103  HCB3225KF-151T50_2P  [5A_Z150_1210_2P]  41.84 47.82 270 top
PL200  1UH_11A_20%_7X7X3_M  [L_7X7X3_M_2P]  78.95 18.15 180 bottom
PL201  HCB3225KF-151T50_2P  [5A_Z150_1210_2P-NPM]  70.02 26.46 270 top
PL301  1UH_6.6A_20%_5X5X3_M  [L_5X5X3_M_2P]  129.64 118.91 0 bottom
PL302  HCB3225KF-151T50_2P  [5A_Z150_1210_2P-NPM]  126.42 131.59 270 top
PL501  1UH_6.6A_20%_5X5X3_M  [L_5X5X3_M_2P]  172.33 28.94 90 bottom
PL601  0.68UH +-20% 7.9A  [L_5X5X3_M]  121.13 114.8 90 bottom
PL602  HCB3225KF-151T50_2P  [5A_Z150_1210_2P]  109.92 130.7 90 bottom
PL603  .15UH +-20% 29A 7X7X4 MOLDING  [L_7X7X4_M]  112.88 114.2 90 bottom
PL604  .15UH +-20% 29A 7X7X4 MOLDING  [L_7X7X4_M]  58.22 59.04 270 bottom
PL605  .15UH +-20% 29A 7X7X4 MOLDING  [L_7X7X4_M]  68.51 52.32 270 bottom
PL606  HCB3225KF-151T50_2P  [5A_Z150_1210_2P]  59.11 38.48 270 top
PL700  4.7UH_5.5A_20%_7X7X3_M  [L_7X7X3_M_2P]  120.48 160.85 0 bottom
PL704  1UH_PCMB042T-1R0MS_4.5A_20%  [CYNTE_PCMB042T-1R0MS_2P]  119.42 154.1 0 bottom
PL1101  HCB3225KF-151T50_2P  [5A_Z150_1210_2P]  150.95 116.89 90 top
PL1102  0.22UH_24A_20%_7X7X4_MOLDING  [L_7X7X4_M]  183.55 99.69 180 bottom
PL1103  0.22UH_24A_20%_7X7X4_MOLDING  [L_7X7X4_M]  183.55 108.33 180 bottom
PL1201  0.68UH_PCMB062D-R68MS_12A_20%  [CYNTE_PCMB062D-R68MS_2P]  40.95 54.23 0 bottom
PL1202  HCB3225KF-151T50_2P  [5A_Z150_1210_2P]  32.95 48.96 90 top
PL1401  1UH_PCMB061H-1R0MS_7A_20%  [CYNTE_PCMB061H-1R0MS_2P]  129.36 142.29 90 bottom
PL1402  HCB3225KF-151T50_2P  [5A_Z150_1210_2P-NPM]  137.07 138.59 180 top
PQ1  L2N7002DW1T1G_SC88-6  [2N7002DW-T-R7_SOT363-6]  132.02 175.11 180 top
PQ2  L2N7002DW1T1G_SC88-6  [2N7002DW-T-R7_SOT363-6]  119.97 170.19 270 top
PQ3  -  [L2N7002WT1G_SC70-3]  149.4 169.41 270 top
PQ5  MMST3904-7-F_SOT323  [RHU002N06_SOT323-3]  90.16 155.7 0 top
PQ6  FDV301N_G 1N SOT23-3  [FDV301N_NL_SOT23-3]  93.91 154.08 180 top
PQ201  -  [AON7934_DFN3X3A8-10]  68.26 17.95 0 bottom
PQ601  AON7934_DFN3X3A-8-10  [AON7934_DFN3X3A8-10]  120.06 124 90 bottom
PQ704  AON7408L_DFN8-5  [SIS412DN-T1-GE3_POWERPAK8-5]  122.83 157.77 180 top
PQ708  AON7506_DFN33-8-5  [SIS412DN-T1-GE3_POWERPAK8-5]  124.94 159.41 90 top
PQ709  -  [L2N7002WT1G_SC70-3]  81.52 167.46 270 top
PQ710  -  [LMUN5113T1G_SOT323-3]  116.87 164.57 180 top
PQ711  -  [LTC015EUBFS8TL_UMT3F]  117.01 160.68 90 top
PQ712  -  [L2N7002WT1G_SC70-3]  80.22 165.57 180 top
PQ717  MDU1512RH_POWERDFN56-8-5  [SIR472DP-T1-GE3_POWERPAK8-5]  128.58 156.72 0 bottom
PQ718  MDU1512RH_POWERDFN56-8-5  [SIR472DP-T1-GE3_POWERPAK8-5]  72 170.01 0 top
PQ720  -  [RUM002N02GT2L_VMT3]  69.65 167.83 180 top
PQ721  -  [RUM002N02GT2L_VMT3]  70.16 160.45 270 top
PQ740  MDU1512RH_POWERDFN56-8-5  [SIR472DP-T1-GE3_POWERPAK8-5]  75.82 165.84 180 top
PQ1101  AON6552_DFN5X6-8-5  [SIR472DP-T1-GE3_POWERPAK8-5]  174.71 96.29 270 bottom
PQ1102  AON6554_DFN5X6-8-5  [SIR472DP-T1-GE3_POWERPAK8-5]  169.37 98.48 90 bottom
PQ1103  AON6554_DFN5X6-8-5  [SIR472DP-T1-GE3_POWERPAK8-5]  169.37 102.29 270 top
PQ1104  AON6552_DFN5X6-8-5  [SIR472DP-T1-GE3_POWERPAK8-5]  174.71 114.25 270 bottom
PQ1105  AON6554_DFN5X6-8-5  [SIR472DP-T1-GE3_POWERPAK8-5]  169.37 108.31 270 top
PQ1106  AON6554_DFN5X6-8-5  [SIR472DP-T1-GE3_POWERPAK8-5]  169.37 104.5 90 bottom
PR2  1M_0402_1%  [R_0402]  131.45 176.53 180 top
PR3  2.2K_0402_5%  [R_0402]  93.48 150.24 180 top
PR4  33_0402_5%  [R_0402]  95.26 150.24 180 top
PR5  3.3K_1206_5%  [R_1206]  128.96 173.29 90 top
PR6  100K_0402_1%  [R_0402]  91.18 158.62 0 top
PR7  1M_0402_1%  [R_0402]  134.04 173.53 90 top
PR8  10K_0402_1%  [R_0402]  90.04 154.43 0 top
PR9  15K_0402_1%  [R_0402]  89.27 158.62 0 top
PR10  1M_0402_1%  [R_0402]  133.15 174.45 270 top
PR11  100K_0402_1%  [R_0402]  90.94 152.91 180 top
PR12  0_0402_5%  [R_0402]  132.53 178.44 180 top
PR13  0_0402_5%  [R_0402]  132.46 177.5 180 top
PR15  200_0402_5%  [R_0402]  157.41 176.48 270 top
PR16  10K_0402_1%  [R_0402]  117.35 167.77 180 top
PR18  100_0402_5%  [R_0402]  159.19 176.48 270 top
PR20  100_0402_5%  [R_0402]  158.3 176.48 270 top
PR28  10K_0402_1%  [R_0402]  116.44 168.66 0 top
PR29  100K_0402_1%  [R_0402]  117.35 169.54 180 top
PR31  1M_0402_1%  [R_0402]  122.31 167 180 top
PR32  100K_0402_1%  [R_0402]  145.61 170.24 180 top
PR33  1M_0402_1%  [R_0402]  121.39 167.89 0 top
PR100  0_0603_5%  [R0603_0OHM]  30.18 37.67 180 bottom
PR102  499K_0402_1%  [R_0402]  37.05 42.46 0 top
PR103  499K_0402_1%  [R_0402]  37.05 41.57 0 top
PR106  4.7_1206_5%  [R_1206]  34.55 33.43 0 bottom
PR107  10K_0402_1%  [R_0402]  37.97 40.68 180 top
PR108  1K_0402_5%  [R_0402]  39.22 40.69 270 bottom
PR109  150K_0402_1%  [R_0402]  37.97 38.9 180 bottom
PR110  150K_0402_1%  [R_0402]  37.05 39.79 0 bottom
PR111  0_0603_5%  [R0603_0OHM]  41.76 37.72 180 bottom
PR112  4.7_1206_5%  [R_1206]  47.43 33.02 0 bottom
PR113  10K_0402_1%  [R_0402]  37.97 39.79 180 top
PR114  2.2K_0402_5%  [R_0402]  49.64 40.16 180 top
PR115  150K_0402_1%  [R_0402]  49.69 38.99 180 bottom
PR116  0_0402_5%  [R0402_0OHM]  49.66 43.87 0 top
PR117  1K_0402_5%  [R_0402]  50.98 40.77 270 bottom
PR118  150K_0402_1%  [R_0402]  48.77 39.85 0 bottom
PR120  0_0402_5%  [R0402_0OHM]  48.7 38.99 0 top
PR121  0_0402_5%  [R0402_0OHM]  37.05 38.9 0 top
PR122  1M_0402_5%  [R_0402]  47.74 43.84 0 top
PR200  0_0603_5%  [R0603_0OHM]  62.99 18.92 90 top
PR201  0_0402_5%  [R0402_0OHM]  54.4 21.3 0 top
PR202  0_0402_5%  [R0402_0OHM]  54.4 23.96 0 top
PR203  4.7_1206_5%  [R_1206]  74.03 23.43 180 bottom
PR204  100K_0402_1%  [R_0402]  55.31 24.89 180 top
PR205  11K_0402_1%  [R_0402]  59.05 16.12 90 top
PR206  5.1_0603_5%  [R_0603]  55.24 15.88 90 top
PR207  60.4K_0402_1%  [R_0402]  56.31 25.08 0 top
PR208  453K_0402_1%  [R_0402]  54.4 20.41 0 top
PR209  10K_0402_1%  [R_0402]  54.4 19.52 0 top
PR210  2.2_0603_5%  [R_0603]  56.51 17.27 270 top
PR301  0_0402_5%  [R0402_0OHM]  132.98 128.4 270 bottom
PR302  1M_0402_1%  [R_0402]  131.97 127.51 90 bottom
PR303  0_0402_5%  [R0402_0OHM]  135.25 124.4 180 bottom
PR304  0_0402_5%  [R0402_0OHM]  135.25 129.92 180 bottom
PR305  0_0402_5%  [R_0402]  134.36 128.98 0 bottom
PR306  0_0603_5%  [R0603_0OHM]  127.48 124.03 180 bottom
PR307  4.7_1206_5%  [R_1206]  126.51 121.56 270 bottom
PR309  21.5K_0402_1%  [R_0402]  134.36 127.12 0 bottom
PR310  31.6K_0402_1%  [R_0402]  134.36 128.05 0 bottom
PR501  0_0402_5%  [R0402_0OHM]  175.39 26.61 180 bottom
PR502  1M_0402_5%  [R_0402]  174.55 24.75 90 bottom
PR503  10_0402_5%  [R_0402]  176.38 23.7 180 bottom
PR504  20K_0402_1%  [R_0402]  175.47 22.81 0 bottom
PR505  10K_0402_1%  [R_0402]  175.42 21.89 180 bottom
PR506  4.7_1206_5%  [R_1206]  168.4 27.88 90 bottom
PR601  45.3_0402_1%  [R_0402]  115.63 144.6 90 bottom
PR602  0_0402_5%  [R0402_0OHM]  118.16 142.96 0 bottom
PR603  0_0402_5%  [R0402_0OHM]  124.77 145.68 270 bottom
PR604  75_0402_1%  [R_0402]  116.52 144.6 90 bottom
PR605  100_0402_1%  [R_0402]  117.42 144.48 90 bottom
PR606  0_0402_5%  [R0402_0OHM]  113.84 145.36 0 bottom
PR607  0_0402_5%  [R0402_0OHM]  119.2 144.48 90 bottom
PR608  78.7K_0402_1%  [R_0402]  118.42 144.47 90 top
PR609  0_0402_5%  [R0402_0OHM]  118.31 144.48 90 bottom
PR610  10K_0402_1%  [R_0402]  111.88 142.53 270 top
PR611  48.7K_0402_1%  [R_0402]  119.31 144.47 90 top
PR612  1.91K_0402_1%  [R_0402]  114.74 145.39 270 top
PR613  88.7K_0402_1%  [R_0402]  114.3 142.72 180 bottom
PR615  0_0402_5%  [R_0402]  110.1 136 90 top
PR617  4.42K_0402_1%  [R_0402]  113.39 139.17 90 bottom
PR618  49.9_0402_1%  [R_0402]  115.76 145.39 270 top
PR619  0_0603_5%  [R_0603]  120.01 130.75 270 bottom
PR621  1K_0402_1%  [R_0402]  110.09 140.74 0 top
PR622  1.96K_0402_1%  [R_0402]  111.88 139.84 90 top
PR623  2K_0402_1%  [R_0402]  110.09 141.63 0 top
PR624  3.65K_0603_1%  [R_0603]  120.78 145.63 270 bottom
PR625  0_0402_5%  [R0402_0OHM]  116.64 145.39 270 top
PR626  10_0402_1%  [R_0402]  117.53 145.39 270 top
PR627  4.7_1206_5%  [R_1206]  120.26 121.98 0 bottom
PR628  4.42K_0402_1%  [R_0402]  109.86 140.08 180 bottom
PR629  95.3K_0402_1%  [R_0402]  114.8 137.77 270 bottom
PR630  4.02K_0402_1%  [R_0402]  119.45 141.17 90 bottom
PR631  27.4K_0402_1%  [R_0402]  110.98 143.41 0 top
PR632  1K_0402_1%  [R_0402]  110.1 137.8 90 top
PR633  11K_0402_1%  [R_0402]  110.17 139.2 270 bottom
PR634  0_0402_5%  [R_0402]  110.1 135.14 270 top
PR635  10K_0402_1%  [R_0402]  114.62 135.39 0 bottom
PR636  1.05K_0402_1%  [R_0402]  121.14 142.33 0 top
PR637  20M_0402_5%  [R_0402]  113.87 138.3 270 bottom
PR638  267_0402_1%  [R_0402]  110.98 137.82 0 top
PR639  3K_0402_1%  [R_0402]  117.47 138 270 bottom
PR640  280_0402_1%  [R_0402]  119.88 134.59 270 top
PR641  1K_0402_1%  [R_0402]  124.45 141.44 90 top
PR642  2.61K_0402_1%  [R_0402]  121.2 140.33 0 bottom
PR643  11K_0402_1%  [R_0402]  122.12 142.39 180 bottom
PR644  1K_0402_1%  [R_0402]  120.77 134.59 270 top
PR645  316_0402_1%  [R_0402]  115.96 134.54 180 top
PR646  316_0402_1%  [R_0402]  121.2 138.52 0 top
PR647  27.4K_0402_1%  [R_0402]  114.61 134.47 0 bottom
PR648  1.5K_0402_1%  [R_0402]  117.25 135.46 180 top
PR649  1.69K_0402_1%  [R_0402]  121.22 139.39 90 top
PR650  2K_0402_1%  [R_0402]  115.45 132.77 0 top
PR651  140K_0402_1%  [R_0402]  119.53 138.25 180 bottom
PR652  2K_0402_1%  [R_0402]  121.2 137.63 0 top
PR653  20M_0402_5%  [R_0402]  116.41 135.46 270 bottom
PR654  20M_0402_5%  [R_0402]  121.44 146.69 0 bottom
PR655  1K_0402_5%  [R_0402]  110.9 128.12 270 top
PR656  11K_0402_1%  [R_0402]  118.19 135.46 270 bottom
PR657  6.04K_0402_1%  [R_0402]  117.3 135.46 270 bottom
PR658  0_0402_5%  [R0402_0OHM]  112.96 145.39 270 top
PR659  0_0402_5%  [R0402_0OHM]  122.1 136.73 180 top
PR660  2.2_0603_5%  [R_0603]  114.23 130.75 270 bottom
PR661  3.65K_0603_1%  [R_0603]  122.32 135.8 180 bottom
PR662  5.11K_0402_1%  [R_0402]  110.83 125.93 270 top
PR663  4.7_1206_5%  [R_1206]  113.85 121.16 180 top
PR664  0_0402_5%  [R_0402]  64.19 44.83 270 bottom
PR665  0_0603_5%  [R_0603]  59.51 43.94 0 bottom
PR666  10_0402_1%  [R_0402]  111.94 132.45 90 top
PR667  3.65K_0603_1%  [R_0603]  113.02 133.67 270 top
PR668  100K_0402_1%  [R_0402]  114.1 132.51 90 top
PR669  4.7_1206_5%  [R_1206]  56.83 52.96 0 top
PR670  100K_0402_1%  [R_0402]  113.15 135.59 270 top
PR671  0_0402_5%  [R0402_0OHM]  70.73 37.35 270 bottom
PR672  2.2_0603_5%  [R_0603]  68.26 35.94 90 bottom
PR673  10_0402_1%  [R_0402]  112.9 137.08 90 bottom
PR674  3.65K_0603_1%  [R_0603]  111.5 135.89 0 bottom
PR675  100K_0402_1%  [R_0402]  111.96 137.29 180 bottom
PR676  4.7_1206_5%  [R_1206]  66.73 46.48 0 top
PR677  100K_0402_1%  [R_0402]  110.17 137.36 270 bottom
PR678  100_0402_1%  [R_0402]  112.97 145.39 270 bottom
PR679  0_0402_5%  [R0402_0OHM]  122.87 128.6 270 bottom
PR680  5.11K_0402_1%  [R_0402]  71.65 37.35 270 bottom
PR681  5.11K_0402_1%  [R_0402]  64.32 45.72 90 bottom
PR682  0_0402_5%  [R0402_0OHM]  111.04 144.36 0 top
PR703  0.01_1206_1%  [R_1206_4P]  111.94 153.42 0 bottom
PR727  10.5K_0402_1%  [R_0402]  105.86 160.53 180 bottom
PR729  392K_0402_1%  [R_0402]  80.96 169.21 90 top
PR731  158K_0402_1%  [R_0402]  105.87 154.31 180 bottom
PR732  53.6K_0402_1%  [R_0402]  80.05 171.01 0 top
PR737  3M_0402_5%  [R_0402]  82.71 169.23 180 top
PR738  1M_0402_1%  [R_0402]  81.79 170.12 0 top
PR740  2_0402_5%  [R_0402]  108.51 152.7 90 bottom
PR741  100K_0402_1%  [R_0402]  104.96 155.19 0 bottom
PR742  2_0402_5%  [R_0402]  112.11 162.78 90 bottom
PR743  10_1206_5%  [R_1206]  116.33 158.5 90 bottom
PR745  100_0402_1%  [R_0402]  113.01 155.19 0 bottom
PR749  200K_0402_1%  [R_0402]  113.01 162.78 90 bottom
PR750  200K_0402_1%  [R_0402]  106.32 162.78 90 bottom
PR751  75K_0402_1%  [R_0402]  114.81 163.58 180 bottom
PR752  66.5K_0402_1%  [R_0402]  107.19 163.7 270 bottom
PR753  182K_0402_1%  [R_0402]  104.94 161.42 0 bottom
PR754  100_0402_1%  [R_0402]  105.45 163.69 270 bottom
PR755  102K_0402_1%  [R_0402]  108.07 163.69 270 bottom
PR756  10K_0402_1%  [R_0402]  109.91 162.1 90 top
PR757  100K_0402_1%  [R_0402]  114.81 161.67 180 bottom
PR760  4.7_0402_5%  [R_0402]  112.71 160.35 270 top
PR761  0_0603_5%  [R0603_0OHM]  117.93 157.38 0 top
PR762  4.02K_0402_1%  [R_0402]  82.76 164.33 0 top
PR763  4.02K_0402_1%  [R_0402]  83.6 169.2 90 top
PR764  10K_0402_1%  [R_0402]  108.96 163.69 270 bottom
PR765  0.01_1206_1%  [R_1206_4P]  128.96 160.53 0 bottom
PR766  4.7_1206_5%  [R_1206]  122.23 163.3 0 top
PR769  0_0402_5%  [R0402_0OHM]  104.96 156.08 0 bottom
PR770  0_0402_5%  [R0402_0OHM]  104.95 157 0 bottom
PR771  0_0603_5%  [R0603_0OHM]  114.93 156.21 0 bottom
PR772  0_0402_5%  [R0402_0OHM]  107.63 152.7 90 bottom
PR773  0_0603_5%  [R0603_0OHM]  132.14 155.83 270 top
PR774  1K_0402_5%  [R_0402]  104.95 158.78 0 bottom
PR775  1K_0402_5%  [R_0402]  104.95 159.66 0 bottom
PR776  0_0402_5%  [R0402_0OHM]  109.84 164.53 0 bottom
PR777  0_0402_5%  [R_0402]  104.95 157.89 0 bottom
PR778  0_0402_5%  [R0402_0OHM]  77.6 165.48 0 top
PR779  0_0402_5%  [R0402_0OHM]  114.81 162.69 180 bottom
PR780  0_0603_5%  [R_0603]  118.67 163.89 270 top
PR781  10K_0402_5%  [R_0402]  70.05 170.87 270 top
PR790  160K_0402_1%  [R_0402]  69.02 161.8 180 top
PR791  10K_0402_5%  [R_0402]  68.13 162.69 0 top
PR801  21.5K_0402_1%  [R_0402]  67.43 30.48 270 bottom
PR802  10K_0402_1%  [R_0402]  66.51 28.71 270 bottom
PR803  0_0402_5%  [R0402_0OHM]  58.1 28.31 90 bottom
PR1101  100K_0402_1%  [R_0402]  157.87 104.08 180 top
PR1103  0_0603_5%  [R0603_0OHM]  164.33 103.76 0 bottom
PR1104  10K_0402_1%  [R_0402]  155.25 112.53 180 top
PR1105  10K_0402_1%  [R_0402]  159.93 101.66 90 bottom
PR1106  10K_0402_1%  [R_0402]  160.84 101.65 90 bottom
PR1107  4.7_1206_5%  [R_1206]  174.89 96.3 180 top
PR1108  3.65K_0603_1%  [R_0603]  155.49 113.67 180 top
PR1110  1_0402_1%  [R_0402]  157.75 115.83 90 bottom
PR1111  100K_0402_1%  [R_0402]  157.87 103.19 180 top
PR1112  100K_0402_1%  [R_0402]  155.37 104.14 135 bottom
PR1113  0_0402_5%  [R_0402]  153.89 105.86 0 bottom
PR1114  1_0603_5%  [R_0603]  161.73 107.31 270 top
PR1115  0_0402_5%  [R_0402]  153.95 107.64 0 bottom
PR1116  0_0402_5%  [R0402_0OHM]  153.95 108.53 0 bottom
PR1117  133K_0402_1%  [R_0402]  153.9 111.19 0 bottom
PR1119  100K_0402_1%  [R_0402]  154.09 110.51 270 top
PR1120  150K_0402_1%  [R_0402]  153.98 112.06 90 bottom
PR1121  13.3K_0402_1%  [R_0402]  154.87 112.98 270 bottom
PR1122  0_0402_5%  [R0402_0OHM]  154.87 109.42 180 bottom
PR1123  0_0603_5%  [R0603_0OHM]  164.39 109.28 0 bottom
PR1124  10K_0402_1%  [R_0402]  156.75 112.53 0 top
PR1125  4.7_1206_5%  [R_1206]  174.89 111.79 180 top
PR1126  3.65K_0603_1%  [R_0603]  156.5 113.67 0 top
PR1128  1_0402_1%  [R_0402]  158.64 115.83 90 bottom
PR1129  301_0402_1%  [R_0402]  160.84 113.04 270 bottom
PR1130  121K_0402_1%  [R_0402]  162.6 111.26 0 bottom
PR1131  2.61K_0402_1%  [R_0402]  155.04 115.18 90 bottom
PR1132  11K_0402_1%  [R_0402]  155.93 115.18 90 bottom
PR1133  1.15K_0402_1%  [R_0402]  160.83 111.25 0 bottom
PR1134  22.1K_0402_1%  [R_0402]  162.62 113.09 90 bottom
PR1135  2K_0402_1%  [R_0402]  161.73 112.13 90 bottom
PR1136  562_0402_1%  [R_0402]  157.58 112.83 270 bottom
PR1137  100_0402_1%  [R_0402]  157.61 113.69 0 bottom
PR1138  0_0402_5%  [R0402_0OHM]  158.98 112.2 90 top
PR1139  0_0402_5%  [R0402_0OHM]  159.87 112.2 90 top
PR1140  32.4K_0402_1%  [R_0402]  158.66 102.57 270 bottom
PR1201  0_0402_5%  [R_0402]  37.59 56.83 90 bottom
PR1202  100K_0402_1%  [R_0402]  38.54 57.72 270 bottom
PR1203  0_0603_5%  [R_0603]  38.86 50.62 270 bottom
PR1204  0_0402_5%  [R_0402]  34.85 56.82 90 bottom
PR1205  100K_0402_1%  [R_0402]  35.74 56.82 90 bottom
PR1206  100K_0402_1%  [R_0402]  33.08 57.73 270 bottom
PR1207  100K_0402_1%  [R_0402]  33.97 56.82 90 bottom
PR1208  4.7_1206_5%  [R_1206]  43.43 58.8 180 bottom
PR1401  100K_0402_5%  [R_0402]  129.31 134.11 90 bottom
PR1402  0_0603_5%  [R0603_0OHM]  132.52 139.13 0 bottom
PR1403  0_0402_5%  [R0402_0OHM]  125.21 132.86 0 bottom
PR1404  1M_0402_1%  [R_0402]  128.34 135 270 bottom
PR1405  0_0402_5%  [R0402_0OHM]  125.21 140.48 0 bottom
PR1406  0_0402_5%  [R_0402]  125.21 133.81 0 bottom
PR1407  0_0402_5%  [R_0402]  126.11 134.73 180 bottom
PR1408  4.7_1206_5%  [R_1206]  127.5 142.68 0 top
PR1410  16.2K_0402_1%  [R_0402]  126.11 136.62 180 bottom
PR1411  10.7K_0402_1%  [R_0402]  126.11 135.67 180 bottom
PU100  SY8286BRAC_QFN20_3X3  [SY8286BRAC_QFN20_3X3-S]  32.48 37.38 0 bottom
PU102  SY8286CRAC_QFN20_3X3  [SY8286CRAC_QFN20_3X3-S]  44.16 37.56 0 bottom
PU200  RT8207PGQW_WQFN20_3X3  [RT8207PGQW_WQFN20_3X3-S]  59.43 22.48 180 top
PU300  SY8286RAC_QFN20_3X3  [SY8286RAC_QFN20_3X3-S]  129.47 123.65 0 bottom
PU500  RT8061AZQW_WDFN10_3X3  [SY8033BDBC_DFN10_3X3-S]  171.33 26.43 0 bottom
PU602  ISL95859HRTZ-T_TQFN40_5X5  [ISL62883CHRTZ-T_TQFN40_5X5-S]  113.98 141.88 270 top
PU603  -  [AOZ5019QI_QFN23_5X3P5]  111.51 127.93 0 bottom
PU604  -  [AOZ5019QI_QFN23_5X3P5]  62.29 45.4 180 bottom
PU605  -  [AOZ5019QI_QFN23_5X3P5]  69.82 38.66 180 bottom
PU606  ISL95808HRZ-TS2378_DFN8_2X2  [ISL95808HRZ-TS2378_DFN8_2X2-S]  121.35 132.16 0 bottom
PU703  ISL88739HRZ-T_QFN32_4X4  [ISL95520HRZ-T_QFN32_4X4-S]  107.93 157.22 0 bottom
PU800  RT9059GSP_SO8  [RT904225GSP_SO8]  59.77 28.01 90 bottom
PU1100  ISL62771HRTZ-T_TQFN40_5X5  [ISL62771HRTZ-T_TQFN40_5X5-S]  156.87 105.14 90 bottom
